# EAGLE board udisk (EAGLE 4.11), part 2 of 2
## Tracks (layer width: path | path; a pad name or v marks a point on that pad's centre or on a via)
+3V3  (via drill 0.3, 0.3 pad 0.3, 0.61)  (1 unrouted)
  Top 0.254: IC12.59 v166.62,109.22 | IC12.58 166.1,108.7 v166.62,109.22 | v166.62,109.22 C25.1 | 163.05,114.54 IC12.1 162.5,113.6 162.56,113.54 162.56,112.9 162.18,112.52 159.89,112.52 159.5,112.92 IC12.7 | v123.19,71.12 123.44,72.26 123.66,72.48 IC1.115 | R10.2 v172.21,96.52 | 26.67,92.28 IC13.16 | 26.67,92.28 30.15,92.28 31.24,91.19 31.24,89.66 C38.1 v33.27,89.66 | 75.69,109.22 R29.2 77.72,109.22 77.98,108.97 v77.98,109.22 | v64.01,105.16 T1.2 | R26.2 v89.92,109.22 R25.2 | R19.2 v105.41,111 105.16,111.25 | 113.03,113.28 v113.03,111.25 | v234.61,91.24 234.61,90.59 234.63,90.11 X2.36 | 224.54,88.14 v224.54,91.19 | 224.54,88.14 224.47,88.08 X2.44 | 224.54,88.14 224.54,87.38 | 26.67,92.28 26.67,92.2 26.6,92.28 IC13.15
  Top 0.305: IC12.45 161,101 v161.16,100.33 161.16,99.57 161.29,99.44 C26.1 | IC12.18 151.94,111.2 v151.38,111.89 150.24,111.89 149.69,111.93 C27.1 | 163.05,114.54 v163.07,114.55 162.56,115.06 C24.1 | IC1.76 115.71,92.34 v116.71,92.33 C10.1 | IC1.95 116.37,82.84 v115.95,83.31 C11.1 | IC1.75 117.73,92.84 v116.71,93.85 115.57,95 C1.1 114.81,95 | IC1.58 127.79,97.89 v127.76,97.66 C9.1 | C8.1 v131.7,100.97 131.29,100.1 IC1.51 | IC1.50 131.79,99.91 133.1,100.84 133.86,101.6 v133.86,102.49 C7.1 | IC1.24 142.96,87.84 v144.02,87.38 C6.1 | IC1.123 127.79,72.55 v128.27,72.26 C3.1 | IC1.130 131.29,72.55 v131.06,72.52 C4.1 | v123.19,71.12 122.94,70.87 C2.1 | IC1.144 138.29,72.66 v138.56,72.26 C5.1 | 101.6,113.54 R20.2 105.32,113.45 105.41,113.54 R19.2 | 109.47,113.28 109.31,113.45 R18.2 112.86,113.45 113.03,113.28 R17.2 116.67,113.45 116.84,113.28 R16.2 | R11.1 v183.13,105.66 | R12.1 v183.39,99.82
  Top 1.016: v82.55,88.9 82.83,89.18 | 81.53,85.6 81.28,85.09 C13.+ 81.15,84.97 80.26,84.07 | C14.1 80.26,81.79
  Top 1.27: 82.83,89.18 IC11.1 | 81.53,85.6 v82.55,88.9 | 80.26,81.79 80.26,84.07 | v78.49,85.09 81.03,85.09 | v77.98,81.53 80.26,81.53 | v82.55,87.38 v82.55,90.42
+5V  (via drill 0.61)
  Top 0.305: IC6.16 246.13,35.56 246.38,35.81
  Top 0.406: R6.2 v156.21,57.4
  Top 0.61: 246.38,35.81 C19.1 | 214.63,38.61 C18.1 IC5.16 | IC2.16 C15.1 | IC3.16 C16.1 | 29.38,53.76 29.46,53.85 | 29.38,53.76 C22.1 | IC9.16 29.21,53.59 29.38,53.76 | 95.5,34.29 IC10.16 C23.1 | IC8.16 C21.1 | IC7.16 C20.1 | 175.26,35.31 IC4.16 C17.1
+5V_IDE  (via drill 0.61)
  Top 0.254: R28.2 231.14,68.83 | v229.11,68.83 R28.2 | R27.2 232.66,67.31 231.39,67.56 231.05,68.41 R28.2
  Bottom 0.254: J8.1 188.98,63.5 189.48,62.99 228.09,62.99 229.11,64.01 v229.11,68.83
  Bottom 1.27: J8.1 188.72,70.61 191.26,73.15 207.26,73.15 209.55,75.44 213.36,75.44 213.87,74.93 213.87,73.41 | JP3.42 213.87,71.38 213.87,71.37 213.87,73.41 | 213.87,73.41 213.87,73.4 JP3.41
+5V_TRACE  (via drill 0.61)
  Top 1.016: 91.78,88.56 91.18,89.16
  Top 1.676: v89.15,80.77 89.15,84.58 D1.1 91.78,88.56 | v89.15,80.77 C12.+ | 91.18,89.16 IC11.2 | v89.15,80.77 88.9,80.77
  Bottom 1.676: J7.1 J9.1 83.31,73.15 89.15,78.99 v89.15,80.77 86.36,80.77 79.25,73.66 J7.1
A00_L  (via drill 0.61)
  Top 0.254: IC2.20 58.42,46.23 59.69,44.96 59.69,37.59 68.33,28.96 90.42,28.96 90.93,29.46 105.41,29.46 105.66,29.21 v105.66,28.96
  Bottom 0.254: U$1.EH2 108.89,16.59 108.2,17.27 108.2,24.38 106.68,25.91 106.68,28.45 106.17,28.96 v105.66,28.96
A01_L  (via drill 0.61)
  Top 0.254: IC2.19 60.96,46.23 62.23,44.96 62.23,37.08 69.34,29.97 v109.22,29.97 | U$1.EH1 108.89,16.84 v109.7,18.26
  Bottom 0.254: v109.7,18.26 109.73,18.29 109.73,24.89 109.22,25.4 v109.22,29.97
A02_L  (via drill 0.61)
  Top 0.254: IC2.18 63.5,46.23 64.77,44.96 64.77,36.58 70.1,30.99 v114.3,30.99 | U$1.EF1 112.04,17.5 v113.79,18.4
  Bottom 0.254: v113.79,18.4 113.79,19.3 113.79,24.89 114.3,25.4 v114.3,30.99
A03_L
  Bottom 0.254: U$1.EV2 74.05,35.93 71.88,38.1 69.09,38.1 67.31,39.62 67.31,49.28 IC2.17 65.79,51.05
A04_L
  Bottom 0.254: U$1.EU2 77.11,35.92 72.39,40.64 72.39,47.24 71.37,48.26 71.37,50.29 71.12,50.55 IC2.15
A05_L  (via drill 0.61)
  Top 0.254: U$1.EV1 74.17,14.73 v75.18,15.75 | IC2.14 73.91,50.8
  Bottom 0.254: v75.18,15.75 75.58,16.65 75.58,34.94 75.58,35.93 69.85,41.66 69.85,52.83 70.87,53.85 72.64,53.85 73.66,52.83 IC2.14
A06_L  (via drill 0.61)
  Top 0.254: U$1.EU1 77.14,14.66 v78.23,15.75
  Bottom 0.254: v78.23,15.75 78.23,36.58 77.39,37.41 77.39,44.78 76.2,46.23 IC2.13
A07_L
  Bottom 0.254: U$1.EP2 89.92,16.76 88.32,18.36 88.32,27.25 87.38,27.94 84.07,27.94 82.8,29.21 82.8,46.99 82.04,47.75 79.5,47.75 78.74,48.51 IC2.12
A08_L
  Bottom 0.254: IC3.20 90.17,45.47 91.44,44.2 91.44,37.59 | U$1.EN2 93.04,16.18 91.44,17.27 91.44,37.59 | 91.44,37.59 91.44,38.1
A09_L  (via drill 0.61)
  Top 0.254: U$1.ER1 86.87,13.72 86.87,19.3 87.88,20.57 v92.5,20.57
  Bottom 0.254: IC3.19 92.71,45.47 93.98,44.2 93.98,41.66 92.71,40.39 92.71,21.08 arc-8 v92.5,20.57
A10_L  (via drill 0.61)
  Top 0.254: U$1.EP1 89.84,16.69 90.93,18.29 v93.98,18.29
  Bottom 0.254: IC3.18 95.25,45.47 96.52,44.2 96.52,41.91 95,40.39 93.98,40.39 93.47,39.88 93.47,21.59 93.98,20.57 v93.98,18.29
A11_L  (via drill 0.61)
  Top 0.254: U$1.EL1 99.57,13.21 v99.57,18.27
  Bottom 0.254: IC3.17 97.79,45.47 99.06,44.2 99.06,39.62 100.58,38.61 101.6,38.1 101.6,19.81 99.57,18.29 v99.57,18.27
A12_L  (via drill 0.61)
  Top 0.254: U$1.EC1 121.61,16.06 v123.44,17.02 | v123.44,40.13 105.66,40.13 105.16,39.12 v104.14,39.12
  Bottom 0.254: IC3.15 102.87,45.47 104.14,44.2 v104.14,39.12 | v123.44,17.02 v123.44,40.13
A13_L
  Bottom 0.254: IC3.14 105.41,45.47 106.68,44.2 106.68,39.62 105.41,38.1 104.14,36.83 104.14,24.13 102.56,22.56 U$1.EK2
A14_L  (via drill 0.3, 0.61)
  Top 0.254: U$1.EK1 102.56,16.21 103.63,17.27 103.63,18.8 104.65,19.81 111.76,19.81 114.81,22.86 120.4,22.86 v121.41,23.88 | v109.22,38.61 110.24,39.62 120.4,39.62 v121.41,38.1
  Bottom 0.254: IC3.13 107.95,45.47 109.22,44.2 v109.22,38.61 | v121.41,23.88 v121.41,38.1
A15_L
  Bottom 0.254: IC3.12 110.49,45.47 111.76,44.2 111.76,38.61 112.27,38.1 116.84,38.1 118.42,36.53 U$1.ED2
A16_L  (via drill 0.3, 0.61)
  Top 0.254: IC4.20 162.81,34.04 124.46,34.04 v122.43,32 | v122.43,22.61 121.16,21.34 v115.82,21.34
  Bottom 0.254: U$1.EE2 115.24,20.75 v115.82,21.34 | v122.43,22.61 v122.43,32
A17_L  (via drill 0.3)
  Top 0.254: U$1.ED1 118.42,16.82 119.38,18.8 122.68,18.8 v124.71,20.83 | IC4.19 166.37,33.53 164.34,33.53 162.81,32.51 125.48,32.51 v124.71,32
  Bottom 0.254: v124.71,20.83 v124.71,32
B_BBSY_IN  (via drill 0.3)
  Top 0.254: v159,100.84 IC12.41 | v124.21,89.41 123.7,88.9 119.63,88.9 IC1.83 110.94,88.84 98.81,76.71 44.96,76.71 44.2,75.69 44.2,54.36 45.72,53.09 45.72,48.26 44.96,47.75 34.8,47.75 34.29,47.24 IC9.3 34.29,42.93
  Bottom 0.254: v159,100.84 158.24,101.09 150.62,101.09 150.37,101.35 149.61,101.35 149.35,101.6 134.37,101.6 132.33,99.57 132.33,93.73 130.3,92.2 124.97,92.2 124.21,91.44 v124.21,89.41
B_BBSY_OUT
  Top 0.254: IC1.82 110.68,89.34 98.55,77.22 43.94,77.22 43.18,76.2 43.18,49.02 42.67,48.51 32.51,48.51 31.75,47.75 IC9.2
B_BG4_IN  (via drill 0.61)
  Top 0.254: IC1.5 145.43,78.34 146.3,77.47 165.35,77.47 v166.37,76.2
  Bottom 0.254: IC7.2 167.64,44.2 166.37,45.47 v166.37,76.2
B_BG4_OUT  (via drill 0.3)
  Top 0.254: IC1.6 145.95,78.84 v147.32,78.49
  Bottom 0.254: IC8.6 146.05,46.23 147.32,47.24 v147.32,78.49
B_BG5_IN  (via drill 0.61)
  Top 0.254: IC1.7 148.24,79.34 149.35,78.23 168.15,78.23 v168.91,77.72
  Bottom 0.254: IC7.3 170.18,44.2 168.91,45.47 v168.91,77.72
B_BG5_OUT  (via drill 0.61)
  Top 0.254: IC1.8 149.27,79.84 v149.86,79.25
  Bottom 0.254: IC8.7 148.59,45.72 149.86,46.99 v149.86,79.25
B_BR4_OUT  (via drill 0.3)
  Top 0.254: IC1.81 123.11,89.84 123.44,90.42 128.78,90.42 v131.57,86.87
  Bottom 0.254: IC8.2 135.89,46.23 137.16,47.5 137.16,61.21 135.64,62.74 135.64,87.38 135.13,87.88 132.84,87.88 v131.57,86.87
B_BR5_OUT  (via drill 0.3)
  Top 0.254: IC1.80 122.85,90.34 123.19,90.93 129.54,90.93 v131.57,88.39
  Bottom 0.254: IC8.3 138.43,45.97 139.7,47.24 139.7,59.44 136.14,62.99 136.14,87.88 135.38,88.65 132.08,88.65 v131.57,88.39
B_C0_IN  (via drill 0.3, 0.61)
  Top 0.254: IC10.13 102.87,39.88 103.63,40.64 119.38,40.64 120.4,41.66 v120.4,44.7 | IC1.100 116.66,80.34 115.32,79.5 v115.32,78.23
  Bottom 0.254: v120.4,44.7 120.4,66.29 115.32,71.12 v115.32,78.23
B_C0_OUT  (via drill 0.3, 0.61)
  Top 0.254: IC10.14 100.33,39.37 102.11,41.15 116.33,41.15 v117.35,42.16 | IC1.1 141.34,76.34 142.24,75.44 v142.24,69.34 | v117.35,56.13 140.46,56.13 142.75,58.42 v143.51,58.42
  Bottom 0.254: v117.35,42.16 v117.35,56.13 | v142.24,69.34 142.24,62.74 143.51,61.72 v143.51,58.42
B_C1_IN  (via drill 0.3, 0.61)
  Top 0.254: IC1.99 116.4,80.84 114.3,79.5 v114.3,76.2 | IC10.10 110.49,35.31 111.76,36.58 117.35,36.58 v118.87,38.1
  Bottom 0.254: v114.3,76.2 114.3,70.61 118.87,66.04 v118.87,38.1
B_C1_OUT  (via drill 0.3)
  Top 0.254: IC1.2 143.89,76.84 144.78,75.95 v144.78,69.09 | IC10.11 109.22,32.51 111.25,32.51 111.76,33.02 111.76,35.56 112.27,36.07 120.4,36.07 121.92,36.58 124.21,36.58 | 124.21,36.58 123.95,36.58 | 124.21,36.58 v142.24,36.58
  Bottom 0.254: v144.78,69.09 144.78,47.5 142.24,45.72 v142.24,36.58
B_INIT_IN  (via drill 0.3, 0.61)
  Top 0.254: IC1.84 129.08,88.34 130.3,87.12 v130.3,85.34 | v133.6,59.44 v163.58,59.44
  Bottom 0.254: v130.3,85.34 130.3,60.96 v133.6,59.44 | v163.58,59.44 163.58,44.7 IC7.1
B_INTR_OUT  (via drill 0.3)
  Top 0.254: IC1.73 123.08,93.84 124.46,92.46 132.08,92.46 134.62,89.92 v134.62,86.61
  Bottom 0.254: IC8.1 133.35,46.48 134.62,47.75 v134.62,86.61
B_MSYN_IN  (via drill 0.3, 0.61)
  Top 0.254: IC12.37 156.97,101.6 v156.97,100.33 | v124.97,87.38 118.87,87.38 IC1.86 117.57,87.34 117.09,86.87 109.73,86.87 99.06,76.2 46.23,76.2 45.47,75.18 v45.47,55.88
  Bottom 0.254: v156.97,100.33 156.46,100.58 150.37,100.58 150.11,100.84 149.35,100.84 149.1,101.09 134.62,101.09 132.84,99.31 132.84,93.47 130.56,91.69 125.73,91.69 125.22,91.19 125.22,87.63 v124.97,87.38 | v45.47,55.88 37.85,55.88 36.83,54.86 IC9.13
B_MSYN_OUT
  Top 0.254: IC1.74 117.99,93.34 117.86,93.47 117.86,95.25 116.84,96.27 111.25,96.27 110.24,95.25 110.24,91.19 97.79,78.74 36.32,78.74 34.29,76.71 IC9.14
B_NPG_IN  (via drill 0.61)
  Top 0.254: IC1.9 170.1,80.34 171.45,78.99 v171.45,78.74
  Bottom 0.254: IC7.4 172.72,44.2 171.45,45.47 v171.45,78.74
B_NPG_OUT  (via drill 0.61)
  Top 0.254: IC1.10 151.06,80.84 v152.4,81.53
  Bottom 0.254: IC8.8 151.13,45.47 152.4,46.74 v152.4,81.53
B_NPR_OUT  (via drill 0.3)
  Top 0.254: IC1.77 130.16,91.84 v132.33,89.66
  Bottom 0.254: IC8.4 140.97,47.24 142.24,48.51 142.24,61.47 141.48,62.23 137.67,62.23 136.65,63.25 136.65,88.65 135.89,89.41 132.59,89.41 v132.33,89.66
B_PA_IN
  Top 0.254: IC1.96 115.61,82.34 115.06,82.04 107.95,82.04 100.08,74.17 51.56,74.17 50.8,73.15 50.8,53.09 53.09,50.8 53.09,42.42 68.83,24.89 96.27,24.89 96.52,25.15 96.52,27.69 97.03,28.45 99.82,28.45 100.33,27.43 IC10.3
B_PA_OUT
  Top 0.254: IC1.93 117.58,83.84 116.84,85.09 109.47,85.09 99.57,75.18 49.78,75.18 48.77,74.17 48.77,54.1 52.32,50.55 52.32,41.66 54.36,39.37 67.82,24.13 97.03,24.13 97.79,25.91 IC10.2
B_PB_IN  (via drill 0.3)
  Top 0.254: IC1.97 115.88,81.84 115.32,81.53 108.97,81.53 v108.46,81.03 | IC10.6 107.95,27.18 109.22,28.45 110.24,28.45 111.51,29.46 115.32,29.46 116.33,30.73 116.33,31.75 115.32,32.77 113.79,32.77 112.52,32 85.6,32 84.84,32.77 84.84,56.64 85.34,57.15 88.14,57.15 88.9,57.91 88.9,65.28 89.66,66.04 107.95,66.04 v108.46,65.53
  Bottom 0.254: v108.46,65.53 v108.46,81.03
B_PB_OUT  (via drill 0.3)
  Top 0.254: IC1.94 117.38,83.34 116.59,84.58 110.24,84.58 v109.73,84.07 | IC10.5 107.95,28.96 109.98,28.96 111.25,29.97 115.06,29.97 115.82,30.99 115.82,31.5 115.06,32.26 114.05,32.26 112.78,31.5 84.58,31.5 83.82,32.26 83.82,57.15 84.33,57.66 87.88,57.66 88.39,58.17 88.39,65.79 89.15,66.55 109.47,66.55 v109.73,66.29
  Bottom 0.254: v109.73,66.29 v109.73,84.07
B_SACK_IN
  Top 0.254: IC1.87 117.83,86.84 117.09,86.11 109.73,86.11 99.31,75.69 47.5,75.69 46.74,74.68 46.74,54.1 48.26,52.58 48.26,48.01 47.24,46.99 42.93,46.99 41.91,45.97 IC9.6
B_SACK_OUT  (via drill 0.61)
  Top 0.254: IC1.78 115.98,91.34 115.32,90.68 110.49,90.68 98.04,78.23 40.89,78.23 39.37,76.45 v39.37,54.36
  Bottom 0.254: v39.37,54.36 38.1,53.09 38.1,44.45 IC9.5
B_SSYN_IN  (via drill 0.3, 0.61)
  Top 0.254: IC12.38 157.48,101.6 157.48,101.09 157.73,100.58 157.73,100.08 v156.97,99.06 | v126.75,86.11 122.94,86.11 120.4,81.28 119.63,81.28 IC1.98 116.14,81.34 112.78,79.25 106.68,79.25 100.58,73.15 53.34,73.15 52.58,72.14 v52.58,55.88
  Bottom 0.254: v156.97,99.06 154.94,99.06 153.92,100.08 150.11,100.08 149.86,100.33 149.1,100.33 148.84,100.58 135.13,100.58 133.35,99.06 133.35,93.22 130.81,91.19 127.25,91.19 126.75,90.68 v126.75,86.11 | v52.58,55.88 47.5,55.88 44.45,52.83 IC9.10 44.45,50.55
B_SSYN_OUT
  Top 0.254: IC1.79 116.24,90.84 115.32,89.92 110.49,89.92 98.3,77.72 42.93,77.72 41.91,76.45 IC9.11 41.91,50.55
BBSY_L
  Top 0.254: U$1.FD1 48.56,34.49 46.74,36.07 30.48,36.07 29.21,37.85 IC9.1
  Top 0.406: IC9.1 29.21,43.43
BG4_IN  (via drill 0.3)
  Top 0.254: v148.34,18.8 v151.51,18.8
  Bottom 0.254: IC7.19 167.64,45.47 168.91,44.2 168.91,19.56 168.15,18.8 v151.51,18.8 | U$1.DS2 147.01,13.01 146.81,13.21 146.81,17.27 v148.34,18.8
BG4_OUT
  Bottom 0.254: IC8.15 146.05,47.24 144.78,46.23 144.78,36.58 143.76,35.56 143.76,13.21 143.84,13.13 U$1.DT2
BG5_IN
  Bottom 0.254: IC7.18 170.18,45.47 171.45,44.2 171.45,23.88 170.69,22.86 170.69,18.8 169.67,17.78 154.43,17.78 153.42,16.76 153.42,12.19 153.34,12.12 U$1.DP2
BG5_OUT
  Bottom 0.254: IC8.14 148.59,47.24 147.32,45.97 147.32,38.1 149.86,34.54 149.86,12.19 150.19,11.86 U$1.DR2
BR4_L  (via drill 0.61)
  Top 0.254: v134.62,21.84 v172.21,21.84
  Bottom 0.254: U$1.DH2 172.39,21.67 v172.21,21.84 | v134.62,21.84 134.62,46.74 135.64,47.75 135.64,50.29 IC8.19
BR5_L  (via drill 0.61)
  Top 0.254: v137.16,23.37 v174.24,23.37
  Bottom 0.254: U$1.DF2 175.54,21.57 v174.24,23.37 | IC8.18 138.43,47.5 137.16,46.23 v137.16,23.37
BUS_ADDR0
  Top 0.254: IC1.112 122.3,73.53 121.67,73.15 112.52,73.15 110.74,71.37 58.67,71.37 57.15,69.85 57.15,44.96 IC2.1
BUS_ADDR1
  Top 0.254: IC1.113 122.81,73.41 122.68,73.15 121.92,72.64 112.78,72.64 111,70.87 61.21,70.87 59.69,69.34 59.69,46.23 60.96,44.96 IC2.2
BUS_ADDR2
  Top 0.254: IC1.114 123.32,73.91 123.19,72.9 122.17,72.14 113.28,72.14 111.25,70.1 62.99,70.1 62.23,69.34 62.23,46.23 63.5,44.96 IC2.3 63.5,42.93
BUS_ADDR3
  Top 0.254: IC1.116 124.21,72.39 124.21,70.1 123.19,69.34 65.79,69.34 64.77,68.33 64.77,46.23 66.04,44.96 IC2.4
BUS_ADDR4
  Top 0.254: IC1.117 124.71,72.9 124.71,69.85 123.44,68.83 70.61,68.83 69.85,68.33 69.85,44.45 IC2.6
BUS_ADDR5
  Top 0.254: IC1.118 125.22,72.64 125.22,69.6 123.7,68.33 73.41,68.33 72.39,67.31 72.39,44.45 IC2.7
BUS_ADDR6
  Top 0.254: IC2.8 76.2,44.96 74.93,46.23 74.93,66.8 76.2,67.82 123.95,67.82 125.73,69.34 125.73,72.9 125.79,72.96 IC1.119
BUS_ADDR7
  Top 0.254: IC2.9 78.74,45.21 77.47,46.48 77.47,66.55 78.49,67.31 124.21,67.31 126.24,69.09 126.24,72.9 126.29,72.95 IC1.120
BUS_ADDR8
  Top 0.254: IC3.1 88.65,44.7 88.65,54.1 91.44,56.9 91.44,62.48 92.71,63.75 121.92,63.75 126.75,68.58 126.75,73.91 126.79,73.96 IC1.121
BUS_ADDR9
  Top 0.254: IC3.2 92.71,43.94 91.19,45.47 91.19,55.37 92.2,56.39 92.2,61.72 93.47,62.99 122.43,62.99 127.25,67.82 127.25,73.91 127.29,73.95 IC1.122
BUS_ADDR10
  Top 0.254: IC3.3 95.25,44.2 93.98,45.47 93.98,60.96 95.25,62.23 129.79,62.23 131.83,64.01 131.83,66.55 132.21,67.18 132.21,72.26 131.83,72.9 131.83,73.91 131.79,73.95 IC1.131
BUS_ADDR11
  Top 0.254: IC3.4 97.79,44.2 96.52,45.47 96.52,59.94 98.04,61.47 130.05,61.47 132.33,63.75 132.33,66.42 132.72,67.06 132.72,72.64 132.33,73.15 132.33,73.91 132.29,73.96 IC1.132
BUS_ADDR12
  Top 0.254: IC3.6 102.87,43.43 101.6,44.7 101.6,59.18 102.87,60.45 130.05,60.45 132.84,63.25 132.84,66.17 133.22,66.93 133.22,72.9 132.84,73.41 132.79,73.97 IC1.133
BUS_ADDR13
  Top 0.254: IC3.7 105.41,44.2 104.14,45.47 104.14,57.91 105.92,59.69 130.3,59.69 133.48,62.99 133.48,66.04 133.73,66.8 133.73,73.15 133.35,73.53 133.29,73.97 IC1.134
BUS_ADDR14
  Top 0.254: IC3.8 107.95,44.2 106.68,45.47 106.68,57.4 108.2,58.93 130.56,58.93 134.11,62.48 134.11,65.91 134.24,66.42 134.24,73.28 134.29,74.24 IC1.136
BUS_ADDR15
  Top 0.254: IC3.9 110.49,44.2 109.22,45.47 109.22,56.9 110.24,57.91 130.56,57.91 134.75,62.23 134.75,73.15 134.79,73.62 IC1.137
BUS_ADDR16  (via drill 0.61)
  Top 0.254: IC1.138 135.29,63.85 136.65,62.48 v161.04,62.48
  Bottom 0.254: IC4.1 162.05,27.94 161.54,28.45 161.54,61.47 v161.04,62.48
BUS_ADDR17  (via drill 0.61)
  Top 0.254: IC1.139 135.79,65.12 137.41,63.75 v162.56,63.75 | IC4.2 167.64,30.48 167.13,30.99 v163.07,30.99
  Bottom 0.254: v163.07,30.99 162.56,31.5 v162.56,63.75
BUS_ADDR_DIR  (via drill 0.3, 0.61)
  Top 0.254: IC3.11 v127.51,50.8 | v131.83,30.48 136.14,25.91 185.93,25.91 186.44,26.42 186.44,34.04 IC4.11 | IC1.111 121.79,75.56 122.43,76.2 v124.21,76.2 | 81.28,50.55 IC2.11 R13.2
  Bottom 0.254: v131.83,30.48 131.83,41.15 v127.51,50.8 127.51,52.83 124.21,56.13 v124.21,76.2 | IC2.11 83.06,52.58 112.27,52.58 113.03,51.82 IC3.11
BUS_DATA0
  Top 0.254: IC1.18 141.98,84.84 143,83.82 155.45,83.82 156.46,82.8 184.66,82.8 203.2,64.26 203.2,29.46 204.72,27.94 IC5.1
BUS_DATA1
  Top 0.254: IC1.19 142.24,85.34 143.26,84.33 155.7,84.33 156.72,83.31 184.91,83.31 205.87,62.36 205.74,29.46 IC5.2
BUS_DATA2
  Top 0.254: IC1.21 142.01,86.34 143.51,84.84 155.96,84.84 156.97,83.82 185.17,83.82 194.82,74.17 | 194.82,74.17 195.07,73.91 | 194.82,74.17 208.28,60.71 208.28,29.46 IC5.3
BUS_DATA3
  Top 0.254: IC1.22 142.27,86.84 143.76,85.34 156.21,85.34 157.23,84.33 185.42,84.33 210.82,58.93 210.82,29.46 212.34,27.94 IC5.4
BUS_DATA4
  Top 0.254: IC1.23 142.53,87.34 144.02,85.85 156.46,85.85 157.48,84.84 185.67,84.84 216.66,53.85 216.66,37.85 215.9,37.34 215.9,29.46 217.17,28.19 IC5.6
BUS_DATA5
  Top 0.254: IC1.25 154.74,88.34 157.73,85.34 185.93,85.34 218.44,52.83 218.44,29.46 IC5.7
BUS_DATA6
  Top 0.254: IC1.26 155,88.84 157.99,85.85 186.18,85.85 220.98,51.05 220.98,29.46 IC5.8
BUS_DATA7
  Top 0.254: IC1.27 155.26,89.34 158.24,86.36 186.44,86.36 223.52,49.28 223.52,38.35 | IC5.9 224.54,27.94 223.52,29.46 223.52,38.35 | 223.52,38.35 223.52,38.61
BUS_DATA8
  Top 0.254: IC1.28 155.52,89.84 158.5,86.87 186.69,86.87 234.95,38.61 234.95,29.21 IC6.1
BUS_DATA9
  Top 0.254: IC1.29 155.79,90.34 158.75,87.38 186.94,87.38 236.47,37.85 236.98,37.85 237.49,37.34 237.49,29.21 IC6.2
BUS_DATA10
  Top 0.254: IC1.30 156.05,90.84 159,87.88 187.2,87.88 235.97,39.12 238.25,39.12 240.03,37.34 240.03,29.21 IC6.3
BUS_DATA11
  Top 0.254: IC1.31 156.31,91.34 159.26,88.39 187.45,88.39 235.97,39.88 240.03,39.88 242.57,37.34 242.57,29.21 IC6.4
BUS_DATA12
  Top 0.254: IC1.32 156.57,91.84 159.51,88.9 187.71,88.9 235.97,40.64 241.81,40.64 245.11,37.34 245.11,31.75 IC6.6
BUS_DATA13
  Top 0.254: IC1.34 156.33,92.84 159.77,89.41 187.96,89.41 234.44,42.93 248.16,42.93 250.19,40.89 250.19,29.21 IC6.7
BUS_DATA14
  Top 0.254: IC1.35 156.6,93.34 160.02,89.92 188.21,89.92 234.44,43.69 250.44,43.69 252.73,41.4 252.73,29.21 IC6.8
BUS_DATA15
  Top 0.254: IC1.36 156.86,93.84 160.27,90.42 188.47,90.42 234.44,44.45 251.71,44.45 255.27,40.89 255.27,28.96 IC6.9
BUS_DATA_DIR  (via drill 0.3)
  Top 0.254: IC1.16 142.22,83.84 142.75,83.31 155.19,83.31 156.21,82.3 184.4,82.3 201.68,65.02 v201.68,42.67 201.68,41.4 199.9,39.62 R14.2
  Bottom 0.254: v201.68,42.67 226.57,42.67 227.33,41.91 IC5.11 228.35,37.59 257.81,37.59 IC6.11
C0_L  (via drill 0.61)
  Top 0.254: v104.65,20.83 v99.06,20.83
  Bottom 0.254: U$1.EJ2 105.74,16.18 104.65,17.27 v104.65,20.83 | IC10.15 97.79,29.97 99.06,28.7 v99.06,20.83
C1_L
  Bottom 0.254: U$1.EF2 112.04,25.12 111.76,25.4 111.76,30.48 110.49,31.75 106.68,31.75 105.41,33.02 IC10.12
CF_CS0#  (via drill 0.3)
  Top 0.254: IC1.143 137.79,67.19 138.18,66.8 194.06,66.8 194.31,67.06 v194.31,67.31 | X2.7 240.35,78.3 237.74,75.95 236.85,75.06 236.85,64.77 236.09,64.01 219.2,64.01 216.79,66.42 216.79,72.39 217.81,73.41 217.82,73.39 JP3.37
  Bottom 0.254: v194.31,67.31 196.85,67.31 197.36,66.8 215.39,66.8 216.79,68.33 216.79,72.39 217.92,73.39 | 217.92,73.39 217.93,73.41 | 217.92,73.39 JP3.37
CF_CS1#  (via drill 0.3)
  Top 0.254: IC1.142 137.29,66.93 137.92,66.29 v195.83,66.29 | X2.32 239.71,78.8 234.82,73.91 234.82,70.23 234.95,70.1 234.95,65.02 234.31,64.64 219.84,64.64 217.93,66.8 217.93,71.37 JP3.38
  Bottom 0.254: v195.83,66.29 216.41,66.29 217.93,68.07 217.93,71.12 217.87,71.44 JP3.38
CF_INTR
  Top 0.254: X2.37 233.36,79.95 232.92,79.5 227.58,79.5 224.03,75.95 224.03,73.41 224.01,73.39 JP3.31
CF_IORD#  (via drill 0.3)
  Top 0.254: IC1.140 136.29,66.15 137.16,65.28 194.06,65.28 195.07,64.26 v198.88,64.26 | X2.34 237.17,80.2 234.7,77.72 231.65,77.72 230.12,76.2 230.12,73.66 229.85,73.39 | 229.85,73.39 229.62,73.15 | JP3.25 229.85,73.39
  Bottom 0.254: v198.88,64.26 199.39,64.26 200.15,65.28 226.82,65.28 227.58,66.04 227.58,69.6 228.85,70.87 228.85,72.39 229.87,73.41 JP3.25
CF_IOWR#  (via drill 0.3)
  Top 0.254: IC1.141 136.79,66.66 137.67,65.79 194.56,65.79 195.07,65.28 v197.61,65.28 | X2.35 235.9,79.95 234.19,78.23 231.39,78.23 228.85,75.69 228.85,72.9 229.36,72.39 230.89,72.39 231.89,73.39 | 231.89,73.39 231.9,73.41 | JP3.23 231.89,73.39
  Bottom 0.254: v197.61,65.28 199.14,65.28 199.64,65.79 226.06,65.79 226.82,66.55 226.82,71.88 227.33,72.39 228.09,72.39 228.85,73.15 228.85,74.17 229.36,74.68 230.63,74.68 231.9,73.41 231.89,73.39 JP3.23
CF_RESET_N
  Top 0.254: X2.1 247.97,84.52 248.41,84.07 251.46,84.07 254,81.53 J5.2
CPLD_CLK
  Top 0.254: IC12.52 163.61,105.7 162.81,104.9 162.81,104.14 163.07,103.38 163.07,101.85 164.08,100.58 164.08,94.49 162.81,93.47 159.26,93.47 157.73,94.49 138.94,94.49 136.65,93.22 136.65,78.49 136.14,77.98 130.81,77.98 130.3,77.47 130.3,74.42 130.29,74.41 IC1.128
CPU_A0  (via drill 0.3, 0.61)
  Top 0.254: IC1.60 126.79,96.98 126.75,97.03 126.75,104.39 133.6,111 136.4,113.54 152.65,113.54 153.8,112.14 154.69,111 158.24,111 v159,112.01 158.5,112.27 158.5,113.54 IC12.9 | v223.27,112.78 223.27,91.44 223.77,90.42 223.77,89.66 223.84,89.47 X2.20 223.84,78.04 219.96,74.17 219.96,73.41 219.95,73.39 JP3.35
  Bottom 0.254: v159,112.01 160.53,112.01 161.8,112.78 v223.27,112.78
CPU_A1  (via drill 0.3 pad 0.3, 0.61)
  Top 0.254: IC1.61 126.29,104.83 136.02,114.05 152.91,114.05 153.67,113.03 154.94,111.51 157.48,111.51 157.99,112.27 157.99,113.54 158,113.55 IC12.10 158,117.84 v157.73,118.11 | 225.04,120.9 225.04,92.46 225.55,91.95 225.55,90.68 225.11,90.23 X2.19 225.11,78.55 221.74,75.18 221.74,73.66 222,73.41 221.98,73.39 JP3.33 | 225.04,120.9 225.04,121.16 | v225.04,122.43 225.04,120.9
  Bottom 0.254: v157.73,118.11 159.26,122.43 v225.04,122.43
CPU_A2  (via drill 0.3, 0.61)
  Top 0.254: IC1.62 125.79,105.22 135.64,114.55 154.18,114.55 154.43,114.3 154.43,113.03 154.69,112.78 155.96,112.78 v156.46,112.27 156.46,113.54 156.5,113.57 IC12.13 | v226.52,123.49 226.31,122.17 226.31,89.92 226.38,89.85 X2.18 226.38,79.06 222.76,75.44 222.76,70.1 222.25,69.6 220.47,69.6 219.96,70.1 219.96,71.37 219.95,71.39 JP3.36
  Bottom 0.254: v156.46,112.27 155.96,112.78 155.96,118.62 158.24,123.44 v226.52,123.49
CPU_A3
  Top 0.254: IC1.63 125.29,105.61 135.38,115.06 154.69,115.06 154.94,114.81 154.94,113.54 155,113.6 IC12.16
CPU_D0  (via drill 0.3, 0.3 pad 0.3)
  Top 0.254: IC1.37 138.29,95.87 138.43,95.76 139.7,95.25 v147.83,95.25 157.73,95.25 159.51,94.23 162.56,94.23 163.58,95 163.58,100.33 162.5,101.66 IC12.48 | X2.21 222.5,85.85 222.5,77.98 v221.23,76.96
  Bottom 0.254: v147.83,95.25 152.4,95.25 158.75,88.9 188.47,88.9 216.66,80.01 218.95,76.96 v221.23,76.96 237.24,76.96 238,76.2 238,73.66 237.87,73.79 JP3.17
CPU_D1  (via drill 0.3, 0.3 pad 0.3)
  Top 0.254: IC1.38 137.79,96.64 138.94,97.03 139.7,96.01 v149.1,96.01 157.99,96.01 159.77,95 162.05,95 163.07,95.76 163.07,100.08 162,101.4 IC12.47 | X2.22 221.23,81.28 221.23,79.25 v220.98,78.49
  Bottom 0.254: v149.1,96.01 152.4,96.01 158.75,89.66 188.72,89.66 216.66,81.03 218.95,78.49 v220.98,78.49 | v220.98,78.49 221.23,78.49 | JP3.15 239.87,76.36 237.74,78.49 v220.98,78.49
CPU_D2  (via drill 0.3, 0.3 pad 0.3)
  Top 0.254: IC1.39 137.29,96.9 138.94,97.79 139.95,96.77 v147.83,96.77 159.51,96.77 160.27,98.04 160.27,100.58 160.5,101.06 IC12.44 | X2.23 219.96,85.85 219.96,80.77 v219.71,80.26
  Bottom 0.254: v147.83,96.77 152.4,96.77 158.75,90.42 188.98,90.42 216.92,82.04 218.69,80.26 v219.71,80.26 | v219.71,80.26 219.96,80.26 | JP3.13 241.87,75.38 236.98,80.26 v219.71,80.26
CPU_D3  (via drill 0.3, 0.3 pad 0.3)
  Top 0.254: IC1.40 136.79,97.17 138.94,98.55 139.95,97.54 v149.1,97.54 159,97.54 159.77,98.81 159.77,100.84 160,101.37 IC12.43 | X2.2 246.76,86.11 246.76,85.47 246.89,85.34 v246.89,80.52
  Bottom 0.254: v149.1,97.54 152.4,97.54 158.75,91.19 189.23,91.19 216.92,83.06 239.01,83.06 241.3,80.52 v246.89,80.52 246.89,78.49 243.84,75.69 243.84,73.41 243.86,73.39 JP3.11
CPU_D4  (via drill 0.3, 0.3 pad 0.3)
  Top 0.254: IC1.41 136.29,97.43 138.94,99.31 139.95,98.3 v147.83,98.3 155.19,98.3 156.5,101.13 IC12.36 | X2.3 245.36,85.85 v245.36,81.53 245.36,74.93 245.87,74.42 JP3.9
  Bottom 0.254: v147.83,98.3 152.4,98.3 158.75,91.95 189.99,91.95 216.92,83.82 239.78,83.82 241.81,81.53 v245.36,81.53
CPU_D5  (via drill 0.3, 0.3 pad 0.3)
  Top 0.254: IC1.42 135.79,97.69 138.94,100.08 139.95,99.06 148.59,99.06 | 148.59,99.06 v149.1,99.06 | IC12.35 156,101.39 154.69,99.06 148.59,99.06 | X2.4 244.09,85.85 244.09,83.31 243.84,83.06 v243.84,82.55
  Bottom 0.254: v149.1,99.06 152.4,99.06 158.75,92.71 190.75,92.71 216.92,84.58 240.28,84.58 242.06,82.55 v243.84,82.55 247.27,82.55 247.9,81.92 247.9,74.17 JP3.7
CPU_D6  (via drill 0.3, 0.3 pad 0.3)
  Top 0.254: IC1.43 135.29,97.95 138.94,100.84 139.95,99.82 v147.83,99.82 154.43,99.82 155.5,101.65 IC12.34 | X2.5 242.82,86.11 v242.82,84.07
  Bottom 0.254: v147.83,99.82 149.61,99.82 149.86,99.57 152.65,99.57 158.75,93.47 190.75,93.47 216.92,85.34 241.55,85.34 v242.82,84.07 249.3,84.07 249.94,83.44 249.94,73.41 JP3.5
CPU_D7  (via drill 0.3, 0.3 pad 0.3, 0.61)
  Top 0.254: IC1.44 134.79,98.21 138.18,100.84 138.18,103.89 138.49,104.2 IC12.32 155.13,104.2 155.45,103.89 v156.46,103.89 | 241.56,102.11 241.55,101.35 241.55,90.17 241.62,90.11 X2.6 241.62,85.92 241.55,85.85 v241.55,76.96 | 241.56,102.11 241.55,102.36 | 241.55,102.11 | 241.55,102.11 241.56,102.11 | v241.55,103.12 241.55,102.11
  Bottom 0.254: v156.46,103.89 159.26,103.89 160.02,103.12 v241.55,103.12 | v241.55,76.96 242.82,75.95 242.82,72.64 243.08,72.39 250.7,72.39 251.71,73.41 251.97,73.41 251.95,73.39 JP3.3
CPU_D8  (via drill 0.3 pad 0.3, 0.61)
  Top 0.254: IC1.45 134.29,98.48 137.67,101.09 137.67,104.39 137.97,104.7 IC12.31 157.79,104.7 158.24,104.39 159,103.63 160.53,103.63 v160.78,103.89 | X2.47 220.73,90.17 220.73,103.89 220.98,104.14 | v220.98,104.39 220.98,104.14 | JP3.4 251.87,63.15 250.7,61.72 218.19,61.72 205.99,73.91 205.99,107.7 206.76,108.46 220.22,108.46 220.98,107.7 220.98,104.14
  Bottom 0.254: v160.78,103.89 220.47,103.89 v220.98,104.39
CPU_D9  (via drill 0.3 pad 0.3, 0.61)
  Top 0.254: IC1.46 133.79,98.74 137.16,101.35 137.16,104.9 137.46,105.2 IC12.30 158.79,105.2 v159.51,104.65 | X2.48 219.46,89.92 219.46,102.36 | 219.46,102.36 219.46,102.62 | 219.46,102.36 219.46,105.16 219.71,105.41 v219.71,105.66 219.71,107.19 218.95,107.95 207.77,107.95 207.01,107.19 207.01,73.91 218.44,62.48 248.92,62.48 249.87,63.43 JP3.6
  Bottom 0.254: v159.51,104.65 218.69,104.65 v219.71,105.66
CPU_D10  (via drill 0.3 pad 0.3, 0.61)
  Top 0.254: IC1.47 133.29,99 136.65,101.6 136.65,105.41 136.94,105.7 IC12.29 157.52,105.7 v157.73,105.92 | X2.49 218.19,89.92 218.19,104.14 | 218.19,104.14 218.19,104.65 | 218.19,104.14 v218.19,106.68 217.68,107.19 208.53,107.19 208.03,106.68 208.03,73.91 218.69,63.25 247.14,63.25 247.87,63.97 JP3.8
  Bottom 0.254: v157.73,105.92 158.75,105.92 161.54,107.19 167.89,107.19 | 167.89,107.19 168.91,107.19 | 167.89,107.19 217.42,107.19 v218.19,106.68
CPU_D11  (via drill 0.3 pad 0.3, 0.61)
  Top 0.254: IC1.48 132.79,99.26 136.14,101.85 136.14,105.66 136.68,106.2 IC12.28 156.24,106.2 v156.72,106.68 | JP3.10 245.87,71.12 246.89,72.14 246.89,74.68 245.87,75.69 245.87,80.77 246.38,81.28 246.38,81.79 246.06,82.11 X2.27 246.06,89.98 246.13,90.42 246.12,105.92 246.13,105.92 v246.13,106.43
  Bottom 0.254: v156.72,106.68 159,106.68 161.54,107.7 242.32,107.7 243.08,106.43 v246.13,106.43
CPU_D12  (via drill 0.3 pad 0.3, 0.61)
  Top 0.254: IC1.49 132.29,99.52 135.64,102.11 135.64,105.92 136.42,106.7 IC12.27 154.71,106.7 v155.7,107.44 | 243.87,71.15 243.84,71.12 | 243.87,71.15 JP3.12 | 243.87,71.15 244.86,72.14 244.86,80.26 244.35,80.77 244.35,81.79 244.79,82.23 X2.28 244.79,89.85 244.86,89.92 244.86,105.92 244.85,106.68 244.86,106.68 v245.36,107.95
  Bottom 0.254: v155.7,107.44 159.51,107.44 161.54,108.2 242.82,108.2 243.08,107.95 v245.36,107.95
CPU_D13  (via drill 0.3 pad 0.3, 0.61)
  Top 0.254: IC1.53 130.29,96 130.3,96.01 130.3,105.41 134.35,109.2 IC12.22 154.96,109.2 155.7,108.46 158.5,108.46 v158.75,108.71 | v243.84,108.97 243.52,107.76 X2.29 243.52,83.5 242.82,83.06 242.82,81.28 243.59,80.77 243.59,75.18 242.82,74.68 242.82,72.14 241.87,71.18 | 241.87,71.18 241.81,71.12 | 241.87,71.18 JP3.14
  Bottom 0.254: v158.75,108.71 160.27,108.71 162.81,111.25 220.73,111.25 223.27,108.97 v243.84,108.97
CPU_D14  (via drill 0.3 pad 0.3, 0.61)
  Top 0.254: IC1.54 129.79,95.76 129.79,105.66 134.08,109.7 IC12.21 155.48,109.7 155.96,109.22 157.23,109.22 v157.48,109.47 | v242.06,110.24 242.06,104.65 242.82,104.14 242.82,101.85 242.32,101.35 X2.30 242.25,85.79 242.06,85.6 242.06,78.23 242.51,77.79 242.51,76.14 240.79,74.68 240.79,72.14 239.87,71.21 | 239.87,71.21 239.78,71.12 | 239.87,71.21 JP3.16
  Bottom 0.254: v157.48,109.47 160.27,109.47 162.56,111.76 221.23,111.76 223.27,110.24 v242.06,110.24
CPU_D15  (via drill 0.3 pad 0.3, 0.61)
  Top 0.254: IC1.55 129.29,96.01 129.29,105.92 133.82,110.2 IC12.20 156.17,110.2 v156.21,110.24 | v240.28,111.23 240.28,106.93 240.28,101.85 241.05,101.35 241.05,90.17 240.98,90.11 X2.31 240.98,77.92 238.76,75.69 238.76,72.14 237.87,71.25 | 237.87,71.25 237.74,71.12 | 237.87,71.25 JP3.18
  Bottom 0.254: v156.21,110.24 160.27,110.24 162.31,112.27 221.74,112.27 223.27,111.25 239.27,111.25 | 239.27,111.25 239.78,111.25 | v240.28,111.23 239.29,111.23 239.27,111.25
CPU_INT  (via drill 0.3)
  Top 0.254: IC1.67 123.29,107.16 123.44,107.44 v123.95,107.95 | IC12.25 v135.89,107.7
  Bottom 0.254: v135.89,107.7 134.87,107.95 v123.95,107.95
CPU_RD
  Top 0.254: IC1.65 124.29,105.49 135.13,115.57 155.19,115.57 155.45,115.32 155.5,115.01 IC12.15
CPU_WR  (via drill 0.3)
  Top 0.254: IC1.66 123.79,106.65 125.86,108.71 v125.98,108.71 | IC12.23 137.41,108.71 v137.16,108.46
  Bottom 0.254: v137.16,108.46 136.91,108.71 v125.98,108.71
D00_L
  Bottom 0.254: U$1.CS2 216.87,16.31 215.9,18.29 215.9,23.88 | IC5.20 204.47,32.77 205.23,32 207.77,32 208.28,32.51 208.28,37.08 208.79,37.59 212.85,37.59 213.36,37.08 213.36,33.53 215.9,32 215.9,23.88 | 215.9,23.88 215.9,23.37
D01_L
  Bottom 0.254: U$1.CR2 219.96,13.21 220.04,13.28 219.96,13.72 219.96,23.88 218.44,25.4 218.44,32 215.9,33.53 215.9,37.59 214.88,38.61 208.28,38.61 206.76,37.59 206.76,36.07 IC5.19
D02_L
  Bottom 0.254: U$1.CU2 210.46,13.06 210.31,13.21 210.31,24.89 210.82,25.4 210.82,32 209.55,33.02 IC5.18
D03_L
  Bottom 0.254: U$1.CT2 213.69,12.01 213.36,12.19 213.36,32 212.09,33.02 IC5.17
D04_L
  Bottom 0.254: U$1.CN2 226.39,13.03 226.57,13.21 226.57,24.89 226.06,25.4 226.06,30.99 223.52,33.53 223.52,36.83 222.25,38.1 218.44,38.1 217.17,36.83 IC5.15
D05_L
  Bottom 0.254: U$1.CP2 223.19,13.03 223.01,13.21 223.01,23.37 220.98,25.4 220.98,32 219.71,33.02 IC5.14
D06_L  (via drill 0.61)
  Top 0.254: v224.54,16.76 220.98,16.76 219.46,18.29 211.33,18.29 209.8,16.76 v208.28,16.76
  Bottom 0.254: IC5.13 222.25,30.48 223.52,29.21 223.52,25.4 224.54,24.38 v224.54,16.76 | U$1.CV2 207.4,15.38 v208.28,16.76
D07_L
  Bottom 0.254: U$1.CM2 229.54,13.64 229.62,13.72 229.62,32 228.6,33.02 226.06,33.02 224.79,34.29 IC5.12
D08_L
  Bottom 0.254: IC6.20 236.22,33.02 234.95,31.75 233.68,31.75 232.16,30.48 232.16,13.21 232.41,13.46 232.41,7.62 232.48,7.69 U$1.CL2
D09_L
  Bottom 0.254: U$1.CK2 235.91,13.01 235.71,13.21 235.71,23.88 237.49,25.4 237.49,31.75 238.76,33.02 IC6.19
D10_L
  Bottom 0.254: U$1.CJ2 239.09,12.88 238.76,13.21 238.76,23.88 240.03,25.4 240.03,31.75 241.3,33.02 IC6.18
D11_L  (via drill 0.61)
  Top 0.254: v240.79,16.26 241.81,15.24 241.81,8.13 242.27,7.67 | 242.27,7.67 242.32,7.62 | 242.27,7.67 U$1.CH1
  Bottom 0.254: IC6.17 243.84,31.5 244.86,30.48 244.86,25.4 241.3,21.84 241.3,16.76 v240.79,16.26
D12_L
  Bottom 0.254: U$1.CH2 242.32,19.81 247.65,25.4 247.65,31.75 248.92,33.02 IC6.15
D13_L
  Bottom 0.254: U$1.CF2 245.39,20.6 250.19,25.4 250.19,31.75 251.46,33.02 IC6.14
D14_L
  Bottom 0.254: U$1.CE2 248.59,21.26 252.73,25.4 252.73,31.75 254,33.02 IC6.13
D15_L
  Bottom 0.254: U$1.CD2 251.76,21.9 255.27,25.4 255.27,31.75 256.54,33.02 IC6.12
DISK_RESET_N  (via drill 0.3)
  Top 0.254: J6.1 J5.1 | IC1.11 150.17,81.34 151.64,82.8 154.94,82.8 155.96,81.79 184.15,81.79 193.8,72.14 193.8,69.34 v194.31,68.83
  Bottom 0.254: v194.31,68.83 196.34,68.83 197.61,67.56 214.12,67.56 214.88,68.33 214.88,74.42 215.65,75.44 236.22,75.44 236.98,74.68 236.98,70.1 237.74,69.34 257.56,69.34 259.08,70.87 J6.1
DM
  Top 0.254: 53.85,104.14 R22.1 | 53.85,104.14 53.59,103.89 | 53.85,104.14 C41.1 | IC12.56 173.23,107.7 179.58,114.3 179.58,121.92 176.28,125.48 71.63,125.48 51.56,125.48 48.77,121.92 48.77,109.98 53.85,104.14 | 53.85,104.14 54.1,104.14
DMARQ#
  Top 0.254: JP3.21 233.87,73.34 232.92,72.39 232.92,69.09 233.01,69 R28.1
DP
  Top 0.254: R23.1 53.85,99.06 53.85,98.81 | 53.85,98.81 53.85,98.04 54.86,97.03 64.26,97.03 66.46,99.23 | 66.46,99.23 66.55,99.31 63.25,99.31 61.21,101.35 61.21,123.44 62.48,124.71 71.88,124.71 | 66.46,99.23 R24.1 | C40.1 53.59,99.06 53.85,98.81 | IC12.57 172.72,108.2 178.82,114.3 178.82,121.67 176.02,124.71 71.88,124.71 | 71.88,124.71 71.63,124.71
GND  (via drill 0.3, 0.3 pad 0.3, 0.61)
  Top 0.254: IC12.4 161,114.77 v160.66,115.57 161.42,114.68 | 162,114.61 IC12.2 | 161.54,114.68 161.93,114.68 | 161.5,114.64 IC12.3 | 160.5,115.29 IC12.5 | IC12.6 160,114.92 160.53,115.44 | IC1.64 124.79,94.03 v124.84,93.98 | IC12.60 163.55,109.7 v162.81,108.97 | IC12.46 161.54,101.09 162.56,99.82 162.56,97.03 161.29,96.01 v161.29,96.14 | IC12.17 151.97,113.03 147.32,113.03 146.56,112.27 v146.56,111.89 146.56,111.76 | R31.1 127.42,66.71 v128.27,67.56 | 235.87,73.31 235.71,73.15 | JP3.19 235.87,73.31 | 235.87,73.31 236.22,73.66 | 213.87,7.62 213.79,7.69 U$1.CT1 | R4.1 v196.09,43.18 196.09,40.64 197.1,39.62 R14.1 | R5.2 v196.09,50.8 | 156.46,38.35 R3.1 v156.46,36.07 | R1.1 119.13,34.29 119.89,33.53 v119.89,31.5 119.89,31.24 | R7.1 193.71,29.38 194.06,29.46 v196.09,29.46 | v123.7,48.26 123.7,48.51 123.44,48.26 R32.1 | v81.28,36.07 R33.1 | 26.67,89.66 25.13,91.2 IC13.14 25.22,92.28 25.15,92.46 25.15,93.98 24.89,94.23 24.13,94.23 23.83,93.93 IC13.12 | 26.67,89.66 C38.2 | v26.67,88.14 26.67,89.66 | IC13.1 26.85,98.23 27.94,98.81 27.94,99.82 28.45,100.33 30.73,100.33 31.24,99.82 31.24,98.3 C36.2 v33.27,98.55 | C37.2 v33.27,95.25 | v64.01,109.22 R9.1 | v45.47,104.14 C41.2 | 47.41,98.89 47.5,98.81 | 47.41,98.89 C40.2 | v45.21,99.06 47.24,99.06 47.41,98.89 | IC1.52 130.79,95.78 130.81,95.76 v130.81,93.98 | IC1.59 127.29,95.98 127.25,96.01 v127.25,93.98 128.29,95.02 IC1.57 | IC1.33 139.05,92.34 v138.94,92.46 | IC1.17 138.7,84.34 v138.81,84.33 | v138.68,82.3 138.43,82.3 138.47,82.34 IC1.13 | IC1.3 139.57,77.34 v138.43,76.71 | IC1.124 128.29,75.93 v128.27,75.95 | IC1.135 133.79,75.51 v133.6,75.95 131.06,75.95 130.79,75.67 IC1.129
  Top 0.254: IC1.126 129.29,75.69 v128.27,75.95 | X2.39 230.82,87.95 230.89,87.88 v230.89,91.19 | X2.9 237.81,88.08 237.74,88.14 v237.74,91.19 | IC1.125 128.79,75.43 v128.27,75.95 | R13.1 v81.28,57.91
  Top 0.305: 161.93,114.68 162,114.61 | 161.42,114.68 161.54,114.68 161.5,114.64 | 160.59,115.38 160.5,115.29 | 160.59,115.38 v160.66,115.57 | 160.53,115.44 160.59,115.38 | C9.2 v128.02,102.36 | C8.2 v131.95,105.66 | C7.2 v134.37,107.19 | C6.2 v148.59,87.12 | v117.98,70.87 C2.2 | v128.27,67.56 C3.2 | v131.06,67.56 C4.2 | v139.06,67.56 C5.2 | v111.63,92.33 C10.2 | v111.38,83.31 C11.2 | v116.5,87.71 116.59,87.76 116.67,87.84 IC1.85 | v111.63,95 C1.2 | IC1.105 v116.85,77.84 v116.84,77.85 | v161.29,119.38 C32.1 | 185.27,96.52 185.42,96.52 | 185.27,96.52 S1.P2 | S1.P1 179.47,96.52 185.27,96.52
  Top 0.406: C28.2 v171.45,105.41 | C24.2 v164.47,117.35 | C25.2 v171.45,109.47 | v161.29,96.14 C26.2 | S1.P1 179.58,96.74 v177.04,96.77 | C31.2 v147.83,120.9 | v148.34,118.62 C30.2 | v146.56,111.89 C27.2 | C29.2 v159.51,120.14 | v50.8,44.2 R2.1 | R8.1 259.08,22.35 v256.58,22.33 | R30.1 v230.89,23.11
  Top 0.61: v156.21,121.92 C33.1 | C19.2 v246.38,41.66 | v214.63,41.66 C18.2 | C15.2 v68.58,56.9 | C16.2 v100.33,57.15 | C22.2 v29.21,57.15 | C23.2 v88.9,34.29 | C21.2 v143.51,56.9 | C20.2 v175.26,56.64 | C17.2 175.43,40.22 v177.04,40.13
  Top 1.016: U$1.FT1 10.49,18.97 v7.62,20.83 | U$1.ET1 80.34,20.24 v80.26,20.32 | v214.88,16.26 213.87,14.22 213.87,7.62 | 88.9,98.81 v88.9,100.58 | 88.9,98.81 88.9,98.55 | 88.9,98.55 88.9,97.28 | 88.9,98.55 88.77,98.68 | 88.77,98.68 87.12,100.33 90.42,100.33 v90.68,100.58 88.9,98.81 | v86.61,85.09 86.61,84.84 86.36,85.09 | 88.9,98.81 88.77,98.68 | IC11.3 88.9,98.81 | v140.72,19.56 143.76,16.51 143.76,7.37 143.84,7.44 U$1.DT1 | v130.3,19.81 130.3,19.56 127.87,17.13 U$1.EA1
  Top 1.27: C13.- 86.36,85.09 | C14.2 v84.07,81.53
  Top 1.676: C12.- v97.03,80.77 | D1.2 v98.55,84.58
  $GND 0.305: v131.06,67.56 130.81,67.06
  Bottom 0.254: U$1.DC2 185.09,21.67 183.39,23.37 176.78,23.37 175.26,24.89 IC4.5
  Bottom 0.406: 254.94,16.18 v255.02,16.26
  Bottom 1.016: U$1.FC2 51.74,20.5 v51.82,20.57 | U$1.EC2 121.59,16.08 | 121.59,16.08 121.67,16 | 121.59,16.08 v120.4,16.76 | U$1.CC2 254.94,16.18
  other vias: 87.12,100.58
IDE_RESET_N
  Top 0.254: J6.2 254.25,78.49 253.87,78.1 JP3.1
INIT_L  (via drill 0.61)
  Top 0.254: U$1.DL1 162.89,12.52 163.07,12.7 v163.07,20.32
  Bottom 0.254: IC7.20 165.1,45.47 166.37,44.2 166.37,22.35 v163.07,20.32
INTR_L  (via drill 0.3, 0.61)
  Top 0.254: 24.89,18.03 v24.88,58.96 | v54.1,71.63 55.63,72.39 110.24,72.39 112.01,74.42 115.82,74.42 116.33,74.93 v118.87,74.93 | v122.94,52.07 129.79,52.07 131.06,50.8 IC8.20
  Top 0.406: U$1.FM1 26.34,16.59 24.89,18.03
  Bottom 0.254: 24.8,59.09 24.8,69.76 26.92,71.63 v54.1,71.63 | v118.87,74.93 118.87,70.61 122.94,66.29 v122.94,52.07
  Bottom 0.406: v24.88,58.96 24.8,59.09
IORDY
  Top 0.254: JP3.27 227.87,72.93 226.82,71.88 226.82,67.82 228.35,66.04 R27.1
LED_OUT  (via drill 0.61)
  Top 0.254: IC1.69 122.29,102.75 121.41,103.63 80.26,103.63 v79.5,104.39
  Bottom 0.254: LED3.K 78.74,118.87 79.5,118.11 v79.5,104.39
LINE_RX
  Top 0.254: X1.3 25.15,111.76 23.88,113.03 18.8,113.03 18.29,112.52 18.29,99.82 19.81,98.3 21.84,98.3 21.88,98.26 IC13.8
LINE_TX  (via drill 0.61)
  Top 0.254: IC13.13 24.46,92.28 24.38,92.2 v24.38,89.92
  Bottom 0.254: X1.2 22.66,91.64 v24.38,89.92
MICRO_RX
  Top 0.254: IC12.11 157.5,116.31 157.23,116.59 131.06,116.59 129.79,115.82 116.84,106.93 71.63,106.93 70.1,105.92 70.1,87.63 69.6,87.12 36.58,87.12 36.07,87.63 36.07,91.95 34.8,93.22 28.7,93.22 27.18,94.74 22.61,94.74 21.88,94.2 IC13.9
MICRO_TX
  Top 0.254: IC12.14 156,115.53 155.45,116.08 131.32,116.08 130.56,115.57 117.09,106.43 72.14,106.43 70.61,105.41 70.61,86.87 70.1,86.36 67.31,86.36 | IC13.11 23.18,87.06 23.88,86.36 67.31,86.36 | 67.31,86.36 67.82,86.36
MSYN_L  (via drill 0.61)
  Top 0.254: IC9.15 31.5,50.8 30.48,49.78 30.48,38.1 30.99,37.08 53.34,37.08 66.29,22.35 113.28,22.35 115.32,24.13 115.57,24.38 v116.59,24.38 | v116.84,18.29 115.24,17.2 U$1.EE1
  Bottom 0.254: v116.59,24.38 117.35,23.37 117.35,19.81 v116.84,18.29
N$1  (via drill 0.61)
  Top 0.254: IC9.7 44.45,45.21 45.21,45.97 47.5,45.97 49.28,47.75 50.8,47.75 | 50.8,47.75 R2.2 | 50.8,47.75 v50.8,50.04
  Bottom 0.254: IC9.9 50.29,50.8 50.8,50.29 v50.8,50.04
N$2
  Top 0.254: IC10.7 110.49,27.69 112.01,28.96 115.57,28.96 116.84,30.48 116.84,34.04 117.35,34.04 117.26,34.12 R1.2 IC10.9
N$3
  Top 0.254: LED3.A 76.2,114.3 73.91,112.01 73.91,109.22 R29.1
N$4
  $+5V 0.61: 153.67,107.95 156.21,105.41 167.39,105.41 167.39,107.95 165.1,107.95 165.1,110.49 166.37,110.49 166.37,114.81 165.61,115.06 164.08,115.06 164.08,114.3 163.58,113.54 161.8,113.54 161.8,116.08 157.73,120.65 153.67,120.65 152.15,119.13 152.15,115.06 153.67,113.03 153.67,107.95
N$5
  Top 0.254: R31.2 129.03,64.77 129.79,65.53 IC1.127
N$6
  $+5V 1.016: 1.27,60.96 264.16,60.96 264.16,127 1.27,127 1.27,60.96
N$7
  Top 0.254: IC7.10 R4.2
N$8
  Top 0.254: R3.2 156.46,40.13 156.21,40.39 IC8.10
N$9
  Top 0.254: IC7.11 R5.1
N$10
  Top 0.406: 156.21,53.85 R6.1 IC8.11
N$11
  Top 0.254: R7.2 189.48,29.46 IC4.10
N$12
  Top 0.406: R8.2 259.59,26.92 IC6.10
N$13  (via drill 0.3)
  Top 0.254: v121.16,85.6 120.9,85.85 118.87,85.85 118.86,85.84 IC1.89
  Bottom 0.254: JP1.5 99.82,90.93 105.16,85.6 v121.16,85.6
N$14  (via drill 0.3)
  Top 0.254: IC1.20 138.7,85.84 v138.05,86.36
  Bottom 0.254: JP1.4 102.36,90.42 105.92,86.87 121.67,86.87 123.44,85.09 123.44,83.06 124.21,82.55 128.02,82.55 128.78,83.31 128.78,86.61 130.05,87.88 130.56,89.41 132.33,90.93 135.64,90.93 137.16,89.41 137.16,86.87 v138.05,86.36
N$15  (via drill 0.3)
  Top 0.254: IC1.104 119.25,78.36 124.33,78.36 124.97,78.99 v124.97,83.82
  Bottom 0.254: JP1.3 104.9,89.66 106.68,87.88 115.06,87.88 115.57,88.39 121.16,88.39 124.97,84.33 v124.97,83.82
N$16  (via drill 0.3)
  Top 0.254: IC1.4 139.08,77.84 v138.94,77.98
  Bottom 0.254: JP1.2 107.44,89.41 107.95,88.9 114.05,88.9 | 114.05,88.9 114.3,88.9 | v138.94,77.98 137.67,78.49 137.67,84.84 139.19,85.85 139.19,88.65 135.89,91.69 132.33,91.69 130.05,89.66 129.54,88.14 128.02,86.61 128.02,85.09 127.51,84.58 125.73,84.58 121.67,88.9 114.05,88.9
N$17
  Top 0.254: LED2.A 86.36,112.27 85.34,111.25 85.34,109.47 85.6,109.22 R26.1
N$18
  Top 0.406: R30.2 229.36,27.94 IC5.10
N$20
  Top 0.254: R33.2 IC2.10
N$21
  Top 0.254: IC12.55 164.35,107.18 165.35,107.19 R11.2
  Top 0.305: R11.2 179.58,107.19
N$22
  Top 0.254: IC12.50 165.35,104.65 166.37,99.82 167.13,99.06 176.02,99.06 176.78,99.82
  Top 0.305: 176.78,99.82 R12.2
N$24
  Top 0.254: IC12.62 165.87,110.7
  Top 0.305: 165.87,110.7 167.89,115.32 Q1.3
N$25
  Top 0.254: IC3.10 113.03,46.74 114.55,48.26 R32.2
N$26
  Top 0.254: C35.1 22.19,101.77 23.88,100.08 23.88,98.3 23.83,98.25 IC13.5
N$27
  Top 0.254: C34.1 26.76,100.42 25.65,99.82 25.65,98.55 25.84,98.23 IC13.2
N$28
  Top 0.254: C34.2 25.06,100.75 24.64,100.33 24.64,98.81 24.38,98.55 24.48,98.46 IC13.4
N$29
  Top 0.254: IC12.61 166.62,110.2 166.62,110.24
  Top 0.305: Q1.1 171.7,116.84 171.7,114.55 170.69,113.54 168.15,113.54 166.62,110.24
N$30
  Top 0.305: IC12.63 165.3,111.2 165.61,111.51 165.61,118.24 164.68,119.17 C32.2 164.68,121.75 164.78,121.85 R15.2
N$31
  Top 0.254: C35.2 20.49,101.18 21.59,100.08 22.61,100.08 23.11,99.57 23.11,98.04 23.18,98.11 IC13.6
N$32
  Top 0.305: C33.2 R15.1
N$34
  Top 0.254: IC13.3 25.13,97.04 25.4,96.52 28.96,96.52 29.72,97.28 29.72,98.3 C36.1
N$35
  Top 0.254: IC13.7 22.53,96.09 23.37,95.25 C37.1
N$38
  Top 0.254: R9.2 68.26,113.73 68.83,114.3 68.83,119.38 LED1.K
N$51
  Top 0.254: X3.2 53.32,109.75 53.76,109.31 C39.1 53.76,108.29 55.37,106.68 55.37,103.89 55.46,103.97 R22.2
N$52
  Top 0.254: T1.1 67.33,102.08 68.07,101.35 68.07,99.06 R24.2
N$53
  Top 0.254: X3.3 55.03,117.94 55.37,117.6 55.37,109.22 | 55.37,109.22 C39.2 | R23.2 55.88,99.06 57.4,100.58 57.4,107.19 55.37,109.22
N$70  (via drill 0.61)
  Top 0.254: X2.45 223.27,90.17 222.76,91.19 222.76,108.71 222,109.73 222,122.17 v223.27,124.46
  Bottom 0.254: LED2.K 93.22,123.19 141.73,123.19 147.32,124.46 v223.27,124.46
NPG_IN  (via drill 0.61)
  Top 0.254: U$1.CA1 261.22,18.18 259.08,20.83 223.01,20.83 221.49,22.35 212.85,22.35 209.8,23.88 v198.12,23.88
  Bottom 0.254: IC7.17 172.72,49.78 174.75,47.75 197.1,47.75 198.12,46.74 v198.12,23.88
NPG_OUT  (via drill 0.61)
  Top 0.254: U$1.CB1 258.12,17.73 256.29,19.81 222.76,19.81 221.23,21.34 212.34,21.34 209.3,22.86 198.63,22.86 | 198.63,22.86 197.61,22.86 | IC8.13 151.13,49.02 151.38,48.26 v172.47,48.26 | 198.63,22.86 v196.09,22.86
  Bottom 0.254: v172.47,48.26 173.74,46.74 196.09,46.74 197.1,45.72 197.1,26.42 196.09,25.4 v196.09,22.86
NPR_L  (via drill 0.3, 0.61)
  Top 0.254: 35.56,13.72 35.56,34.04 35.05,35.05 29.97,35.05 27.69,37.85 v27.69,58.93 | v56.39,71.12 57.4,71.88 110.49,71.88 112.52,73.91 v116.84,73.91 | v121.41,54.61 139.7,54.61 140.97,53.34 IC8.17
  Top 0.406: U$1.FJ1 35.89,13.39 35.56,13.72
  Bottom 0.254: v27.69,58.93 27.69,69.09 28.45,69.85 54.1,69.85 v56.39,71.12 | v116.84,73.91 116.84,70.74 121.41,66.29 v121.41,54.61
PA_L
  Top 0.254: U$1.CC1 254.96,14.28 253.75,15.49 253.75,17.78 252.98,18.8 222.5,18.8 220.73,20.57 207.26,20.57 206.76,21.08 195.58,21.08 194.56,22.1 194.56,23.62 193.8,24.38 186.18,24.38 185.42,25.15 135.89,25.15 133.1,27.94 115.82,27.94 114.3,26.42 114.3,25.4 113.79,24.89 104.65,24.89 104.14,25.65 104.14,27.69 103.89,28.96 95.76,28.96 95.25,27.43 IC10.1 95.25,26.42
PB_L
  Top 0.254: U$1.CS1 216.87,16.82 216.15,17.53 211.58,17.53 209.55,15.49 207.52,15.49 206.76,16.26 206.76,19.81 206.25,20.32 195.33,20.32 193.8,21.84 193.8,23.11 193.29,23.62 185.93,23.62 185.17,24.38 135.64,24.38 132.84,27.18 116.08,27.18 115.06,26.16 115.06,25.15 114.3,24.38 104.14,24.38 102.87,26.16 IC10.4
POWER_5V_1
  Bottom 1.016: U$1.CA2 261.22,16.88 J1.1
POWER_5V_2
  Bottom 1.016: U$1.DA2 191.37,13.35 191.01,13.72 J2.1
POWER_5V_3
  Bottom 0.254: 127.36,20.83 J3.1
  Bottom 1.016: U$1.EA2 128.02,13.21 127.36,13.35 127.36,20.83
POWER_5V_4
  Bottom 1.016: U$1.FA2 57.91,13.21 J4.1
RESET#  (via drill 0.3)
  Top 0.254: v151.64,103.38 152.15,103.12 157.99,103.12 IC12.39 157.99,101.6 v158.75,99.06 | v120.65,111.51 R21.2 | v166.37,96.52 R10.1 170.43,92.71 178.82,92.71 S1.P3 179.83,92.71 185.42,92.71 S1.P4
  Bottom 0.254: v151.64,103.38 144.78,112.52 121.41,112.52 120.65,111.76 v120.65,111.51 | v158.75,99.06 159.51,98.3 164.59,98.3 v166.37,96.52
SACK_L
  Bottom 0.406: U$1.FT2 10.49,35.13 13.97,38.61 35.81,38.61 36.83,39.62 IC9.4
SRST#
  Top 0.254: 120.65,115.06 R21.1 120.65,116.59 117.86,119.13 JP2.15
SSYN_L  (via drill 0.61)
  Top 0.254: v40.64,39.12 41.15,38.1 53.85,38.1 66.8,23.37 v106.89,23.37 | U$1.EJ1 105.74,16.18 106.68,16.76 v106.87,18.4
  Bottom 0.254: IC9.12 39.37,49.53 40.64,48.26 v40.64,39.12 | v106.89,23.37 v106.87,18.4
TCK  (via drill 0.3)
  Top 0.254: IC12.53 165.35,106.17 165.61,105.66 166.37,105.66 v168.91,101.35 | R17.1 112.18,115.15 JP2.9
  Bottom 0.254: v168.91,101.35 164.59,101.35 163.32,102.11 151.13,102.11 149.1,104.65 112.78,104.65 112.01,105.66 112.01,115.32 JP2.9
TDI  (via drill 0.3)
  Top 0.254: IC12.33 154.43,102.11 140.97,102.11 v139.95,103.12 | JP2.5 R19.1
  Bottom 0.254: v139.95,103.12 138.18,103.63 107.7,103.63 106.93,104.39 106.93,115.57 JP2.5
TDO  (via drill 0.3)
  Top 0.254: IC12.49 164.34,103.89 164.34,103.38 v164.85,102.36 | R16.1 116.84,115.82 116.59,115.82 JP2.13
  Bottom 0.254: v164.85,102.36 163.83,102.62 151.38,102.62 145.8,109.98 117.6,109.98 116.84,110.74 116.84,115.32 JP2.13
TMS  (via drill 0.3)
  Top 0.254: IC12.51 165.06,105.2 165.86,105.16 v167.89,100.33 | R18.1 109.22,115.57 JP2.7
  Bottom 0.254: v167.89,100.33 164.59,100.33 163.07,101.6 150.88,101.6 148.84,104.14 109.98,104.14 109.47,104.9 109.47,115.32 JP2.7
TRST#
  Top 0.254: R20.1 JP2.3
USB_PUP  (via drill 0.3)
  Top 0.254: T1.3 68.3,105.89 71.12,107.7 93.98,107.7 94.49,107.95 94.49,109.22 R25.1 116.59,109.22 v118.62,111.25 | IC12.19 135.43,110.7 v135.13,111
  Bottom 0.254: v118.62,111.25 118.62,111 119.13,110.49 134.62,110.49 v135.13,111
VDDCORE  (via drill 0.3, 0.3 pad 0.3)
  Top 0.254: IC12.54 164.47,106.68 165.86,106.68 166.12,106.43 v166.5,106.43 | IC12.8 159,114.8 v159.26,115.32 159.51,115.82 C29.1 | v156.75,115.8 156.75,115.29 157,115.03 IC12.12 | IC12.64 164.45,113.14 v164.85,113.54 | IC12.24 v154.69,108.2
  Top 0.305: C28.1 167.64,105.41 166.88,106.43 v166.5,106.43
  Top 0.406: C30.1 v154.18,118.62
  Top 0.61: C31.1 154.43,120.14 v155.19,119.63

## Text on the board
tNames: UDisk V0.1 2006 | Unibus Device Emulator | http://www.heeltoe.com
